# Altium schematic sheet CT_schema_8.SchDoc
size 274 x 160 mm
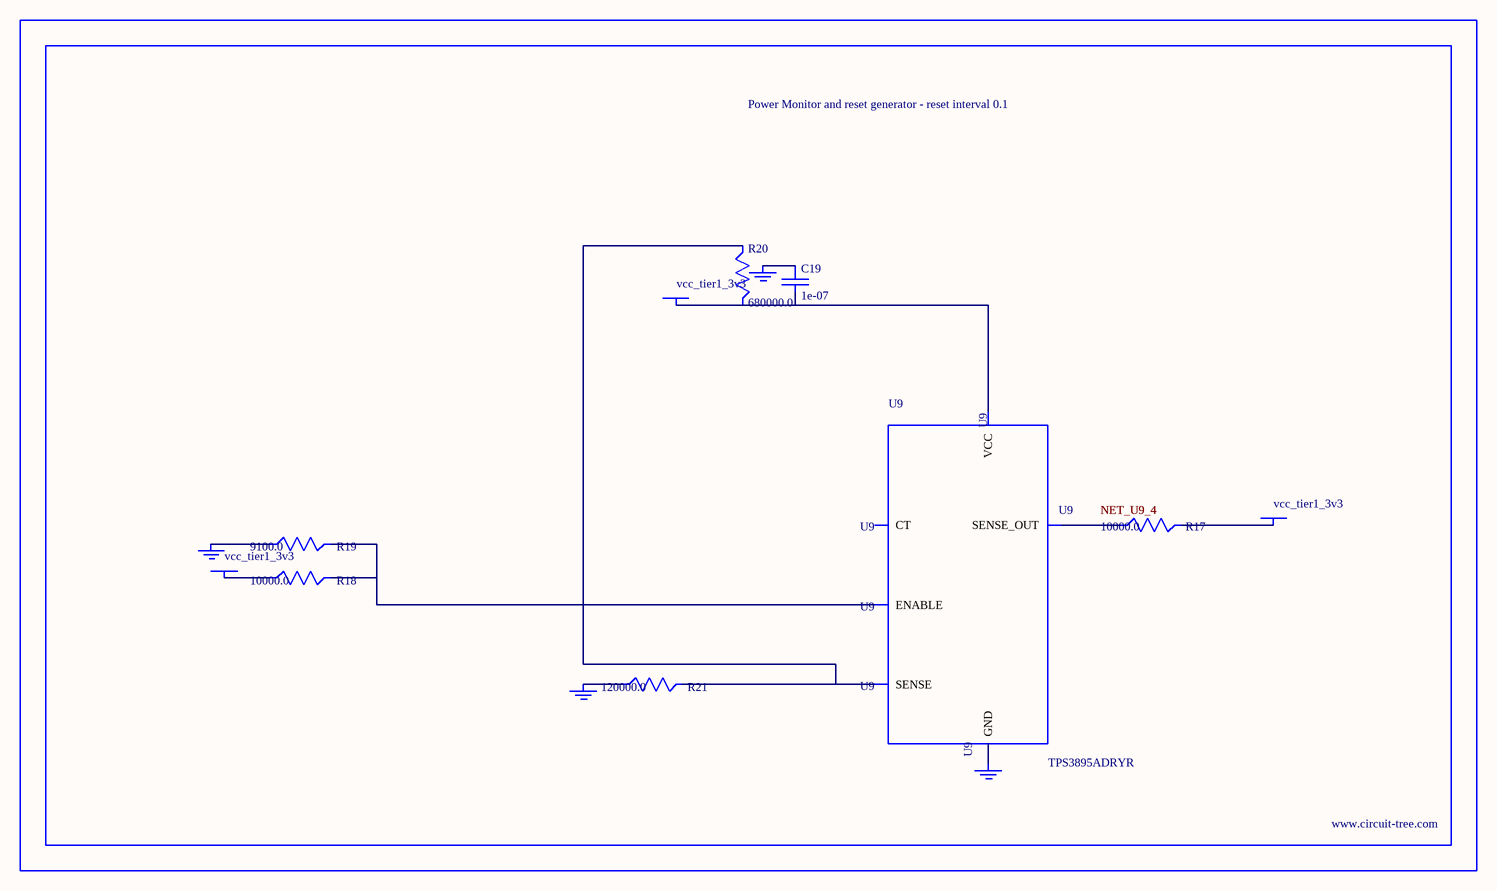
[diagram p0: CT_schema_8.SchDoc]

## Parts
BORDER7  (no value)
C19  1e-07  [C0402]
GND_INSTANCE_7_0  (no value)
GND_INSTANCE_7_1  (no value)
GND_INSTANCE_7_2  (no value)
GND_INSTANCE_7_3  (no value)
POWER_INSTANCE_7_0  vcc_tier1_3v3
POWER_INSTANCE_7_1  vcc_tier1_3v3
POWER_INSTANCE_7_2  vcc_tier1_3v3
R17  10000.0  [R0603]
R18  10000.0  [R0603]
R19  9100.0  [R0603]
R20  680000.0  [R0603]
R21  120000.0  [R0603]
U9  TPS3895ADRYR  [SON-6]

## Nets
NetC19_1: C19.1 GND_INSTANCE_7_2.0(GND)
NetC19_2: C19.2 POWER_INSTANCE_7_2.0(PWR) R20.2 U9.6(VCC)
NetGND_INSTANCE_7_0_0: GND_INSTANCE_7_0.0(GND) R19.1
NetGND_INSTANCE_7_1_0: GND_INSTANCE_7_1.0(GND) R21.1
NetGND_INSTANCE_7_3_0: GND_INSTANCE_7_3.0(GND) U9.2(GND)
NetPOWER_INSTANCE_7_0_0: POWER_INSTANCE_7_0.0(PWR) R18.1
NetPOWER_INSTANCE_7_1_0: POWER_INSTANCE_7_1.0(PWR) R17.2
NetR17_1: R17.1 U9.4(SENSE_OUT)
NetR18_2: R18.2 R19.2 U9.1(ENABLE)
NetR20_1: R20.1 R21.2 U9.3(SENSE)

Not connected (* = marked no-connect by the designer): U9 5(CT)

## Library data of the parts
BORDER7 = BORDER_PAGE7
C19 = C0402C104K3RACTU
GND_INSTANCE_7_0-GND_INSTANCE_7_3 = GND
POWER_INSTANCE_7_0-POWER_INSTANCE_7_2 = PWR
R17 R18 = RC0603JR-0710KL
R19 = RC0603JR-079K1L
R20 = RC0603JR-07680KL
R21 = RC0603JR-07120KL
